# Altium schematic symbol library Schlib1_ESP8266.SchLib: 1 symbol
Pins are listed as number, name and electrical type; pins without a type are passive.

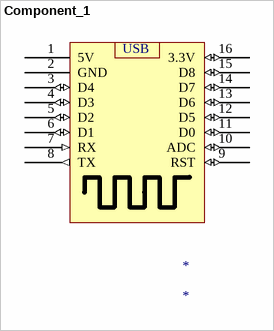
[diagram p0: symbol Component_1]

## Component_1
designator *
pins: 1 5V, 2 GND, 3 D4 (io), 4 D3 (io), 5 D2 (io), 6 D1 (io), 7 RX (in), 8 TX (out), 9 RST (io), 10 ADC (io), 11 D0 (io), 12 D5 (io), 13 D6 (io), 14 D7 (io), 15 D8 (io), 16 3.3V (io)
